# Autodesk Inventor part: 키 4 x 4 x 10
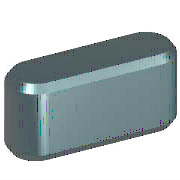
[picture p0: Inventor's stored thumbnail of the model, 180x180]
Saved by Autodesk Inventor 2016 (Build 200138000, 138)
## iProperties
IsCustomPart: 1
Created: 2012-02
Part Number: 키 4 x 4 x 10
Material: 강철, 연강
Description: 키 및 해당 키홈
Document SubType Name: Modeling
Standard: KS B 1311
Designer: mduedu
Standards Organization: KS
Language: ko-KR
Size Designation: 4 x 4 x 10
Categories: <MemberInstance><Categories><Category DisplayName="샤프트 부품" InternalName="7f7aeb1f-a693-4053-b835-cee3144e0d98" Mnemonic="SHFT"><Category DisplayName="키" Interna
Density: 1 g/cm^3
Appearance: 노란색
Author: mduedu
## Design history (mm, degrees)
workplane "Work Plane1"
workplane "Work Plane2"
sketch "스케치1"
  geometry: L1 (2, 2)-(8, 2); L2 (8, -2)-(2, -2); L3 (0, 9.4)-(0, -7.4) reference; L4 (-5, 0)-(30, 0) reference; L5 (10, 0)-(10, 7); A1 r 2 centre (2, 0) between (2, 2) and (2, -2); A2 r 2 centre (8, 0) between (8, -2) and (8, 2)
  constraints: 6 end point, 5 point on circle, 4 tangent, 3 point on line, 2 centre point, 1 horizontal, 1 parallel, 1 perpendicular
  dimensions: "d0" = 2 radius of A1 (= 0.5 x PB); "d13" = 2 radius of A2 (= 0.5 x PB); "d14" = 10 distance between parallel lines of L5 L3 (= NLG)
extrude "본체1" new body sketch "스케치1" taper "d3" = 0 deg; stored distance "d4" = 10
workplane "Work Plane3"
body "Solid1"
chamfer "모따기1" distance "d8" = 0.25 (= PHH); stored, may be unused: second distance "d9" = 0.25 (= PHH), angle "d15" = 45 deg
other parameters: "d1" = -2.5 (= -PNT), "d2" = 1.5 (= PH - PNT), "NLG" = 10 [user parameter; used in 3 equation terms], "PB" = 4 [user parameter; used in 2 equation terms], "PNT" = 2.5 [user parameter; used in 2 equation terms], "PH" = 4 [user parameter; used in 1 equation term], "PHH" = 0.25 [user parameter; used in 2 equation terms], "d10" = 0, "d16" = 0, "d17" = 0, "d18" = 0, "WDMAX" = 12 [user parameter], "RR" = 0.08 [user parameter], "PUEB" = 1.8 [user parameter]
